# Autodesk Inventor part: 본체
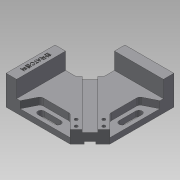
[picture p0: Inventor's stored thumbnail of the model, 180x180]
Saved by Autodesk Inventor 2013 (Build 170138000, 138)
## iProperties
Created: 2019-04
Part Number: 본체
Material: 일반
Document SubType Name: Modeling
Designer: Administrator
Density: 1 g/cm^3
Author: Administrator
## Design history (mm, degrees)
sketch "스케치1"
  geometry: L1 (-60, -60)-(31.716, -60); L2 (60, -60)-(60, -31.716); L3 (60, 60)-(-10, 60); L4 (-60, 60)-(-60, 10); L5 (-60, -60)-(60, 60); L6 (60, -60)-(-60, 60); L7 (-60, 10)-(-29.806, 10); L8 (-10, 10)-(-10, 29.806); L9 (-29.806, 10)-(-9.829, 29.977); L10 (31.716, -60)-(60, -31.716); L11 (-60, 10)-(-60, -60); L12 (-10, 60)-(-60, 60); L13 (-29.806, 10)-(-10, 10); L14 (-10, 29.806)-(-10, 60); L15 (31.716, -60)-(60, -60); L16 (60, -31.716)-(60, 60); 1 further point
  constraints: 32 end point, 9 parallel, 5 perpendicular, 4 horizontal, 2 midpoint, 2 point on line, 2 vertical
  dimensions: "d0" = 120 distance of L4.start L3.start; "d1" = 120 distance of L3.start L2.start; "d2" = 50 distance of L8.start L3.end; "d3" = 93 distance between parallel lines of L9 L10; "d4" = 20 distance from line of L10 L2.start
extrude "돌출1" new body sketch "스케치1" distance "d5" = 42; taper "d6" = 0 deg
sketch "스케치2"
  geometry: L1 (-60, -60)-(31.716, -60) reference; L2 (31.716, -60)-(60, -31.716) reference; L3 (-10, 29.806)-(-29.806, 10) reference; L4 (-60, 10)-(-60, -60) reference; L5 (-40, -60)-(-30, -40); L6 (-30, -40)-(11.716, -40); L7 (-20, -54.5)-(4, -54.5); L8 (-20, -45.5)-(4, -45.5); L9 (45.858, -45.858)-(0, 0); L10 (11.716, -40)-(31.716, -60); A1 r 4.5 centre (-20, -50) between (-20, -45.5) and (-20, -54.5); A2 r 4.5 centre (4, -50) between (4, -54.5) and (4, -45.5); 2 further points
  constraints: 12 end point, 4 point on circle, 4 tangent, 2 centre point, 2 point on line, 1 equal radius, 1 horizontal, 1 horizontal alignment, 1 midpoint, 1 parallel, 1 perpendicular
  dimensions: "d8" = 20 distance from line of L5.start L4; "d9" = 30 distance from line of L5.end L4; "d10" = 9 diameter of A1; "d11" = 40 distance from line of A1.centre L4; "d12" = 24 distance of A2.centre A1.centre; "d13" = 10 distance from line of L1 A1.centre; "d14" = 20 distance between parallel lines of L1 L6; "d15" = 20 distance between parallel lines of L10 L9; "d16" = 6 distance from line of point (31.716, -51.515) L2; "d17" = 12 distance of point (23.23, -43.029) point (31.716, -51.515); "d18" = 14 distance from line of point (31.716, -51.515) L9; "d19" = 14 distance from line of L9 point (23.23, -43.029)
extrude "돌출2" cut sketch "스케치2" distance "d20" = 34; taper "d21" = 0 deg
extrude "돌출3" cut sketch "스케치2" stored distance "d22" = 34; taper "d23" = 0 deg
sketch "스케치3"
  geometry: L1 (11.716, -40)-(31.716, -60) reference; L2 (31.716, -60)-(60, -31.716) reference; L3 (-10, 29.806)-(-29.806, 10) reference; L4 (-29.806, 10)-(-60, 10) reference; L5 (-60, 10)-(-60, -60) reference; L6 (-60, -60)-(-40, -60) reference; L7 (-40, -60)-(-30, -40) reference; L8 (-30, -40)-(11.716, -40) reference; L9 (-45, -60)-(-45, 10); L10 (-19.903, 19.903)-(45.858, -45.858); 1 further point
  constraints: 4 end point, 2 midpoint, 2 point on line, 1 vertical
  dimensions: "d24" = 15 distance between parallel lines of L9 L5
extrude "돌출4" cut sketch "스케치3" distance "d25" = 24; taper "d26" = 0 deg
sketch "스케치4"
  geometry: L1 (10, 29.806)-(29.806, 10) reference; L2 (-31.716, -60)-(-60, -31.716) reference; L3 (-45.858, -45.858)-(19.903, 19.903); L4 (-31.716, -51.515)-(-23.23, -43.029); 2 further points
  constraints: 4 end point, 4 midpoint, 1 parallel
  dimensions: "d27" = 6 distance from line of L4.start L2; "d28" = 12 distance of L4.start L4.end; "d29" = 14 distance between parallel lines of L4 L3
hole "구멍1" sketch "스케치4" diameter "d31" = 4.5; stored, may be unused: countersink angle "d35" = 90 deg, drill point angle "d37" = 118 deg; dims "d32" = 6, "d33" = 8, "d34" = 10, "d36" = 8
sketch "스케치5"
  geometry: L1 (10, 29.806)-(29.806, 10) reference; L2 (-31.716, -60)-(-60, -31.716) reference; L3 (-41.615, -50.101)-(24.146, 15.66); L4 (-50.101, -41.615)-(15.66, 24.146); 1 further point
  constraints: 4 end point, 4 point on line, 1 parallel, 1 perpendicular
  dimensions: "d38" = 12 distance between parallel lines of L4 L3; "d39" = 6 distance from line of L4 point (0, 0)
extrude "돌출5" cut sketch "스케치5" distance "d40" = 3.5; taper "d41" = 0 deg
sketch "스케치6"
  geometry: L1 (31.716, -60)-(11.716, -40) reference; L2 (60, -31.716)-(31.716, -60) reference; L3 (40, -11.716)-(60, -31.716) reference; L4 (40, 30)-(40, -11.716) reference; L5 (60, 40)-(40, 30) reference; L6 (60, 45)-(60, 40) reference; L7 (60, 45)-(-10, 45) reference; L8 (-10, 29.806)-(-10, 45) reference; L9 (-29.806, 10)-(-10, 29.806) reference; L10 (-45, 10)-(-29.806, 10) reference; L11 (-45, -60)-(-45, 10) reference; L12 (-40, -60)-(-45, -60) reference; L13 (-30, -40)-(-40, -60) reference; L14 (11.716, -40)-(-30, -40) reference; C1 r 2.25 at (31.716, -51.515) reference; C2 r 2.25 at (23.23, -43.029) reference; 1 further point
node "작업 평면1"
sketch "스케치7"
  geometry: L1 (60, -31.716)-(31.716, -60) reference; L2 (-29.806, 10)-(-10, 29.806) reference; L3 (-25.56, 14.246)-(40.201, -51.515); L4 (-14.246, 25.56)-(51.515, -40.201); 1 further point
  constraints: 4 end point, 4 point on line, 2 perpendicular
  dimensions: "d42" = 16 distance between parallel lines of L4 L3; "d43" = 8 distance from line of point (0, 0) L4
extrude "돌출6" cut sketch "스케치7" distance "d44" = 3.5; taper "d45" = 0 deg
fillet "모깎기1" dims "d46" = 5
sketch "스케치8"
  geometry: L1 (-45, 10)-(-60, 10) reference; L2 (-60, 10)-(-60, -60) reference; 2 further points
  constraints: 1 other
  dimensions: "d47" = 35 distance from line of L1 point (-52.5, -25); "d48" = 7.5 distance from line of L2 point (-52.5, -25)
feature "엠보싱1" sketch "스케치8" dims "d0" = 120, "d1" = 120, "d2" = 50, "d3" = 93, "d4" = 20, "d49" = 0.5, "d50" = 0
node "솔리드1"
mirror "대칭1"
mirror "대칭2"
